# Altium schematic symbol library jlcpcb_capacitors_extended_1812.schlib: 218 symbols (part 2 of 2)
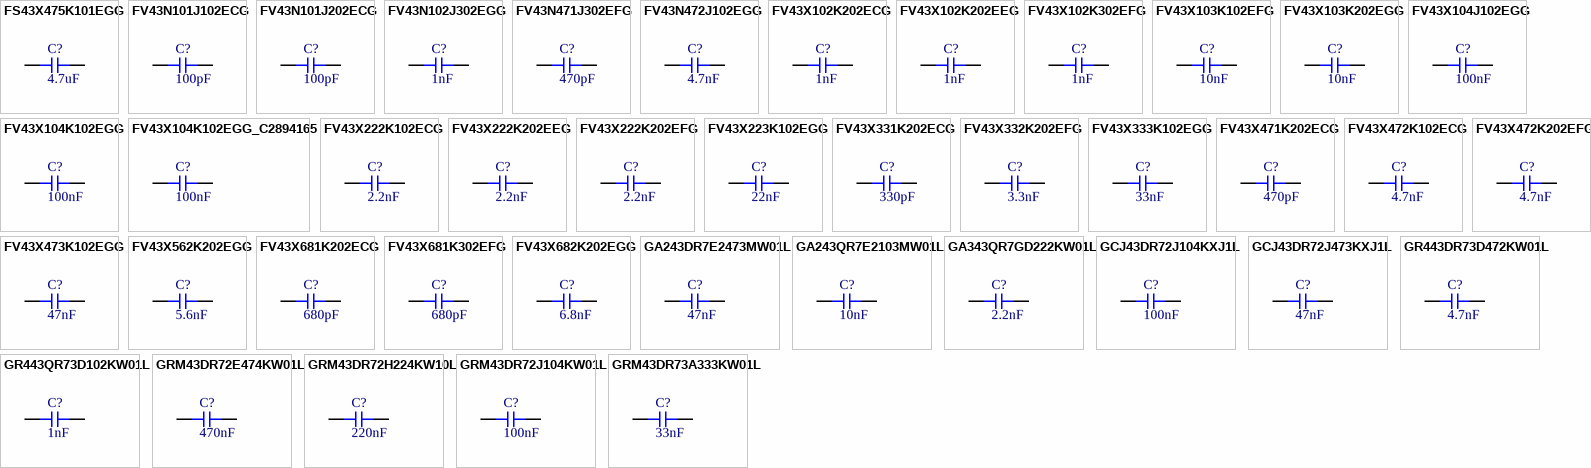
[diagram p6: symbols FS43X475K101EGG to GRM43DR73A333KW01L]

## FV43X333K102EGG
designator C?  Capacitance: 33nF  (hidden comment: *)
Capacitor, Ceramic (MLCC), 33nF, ±10%, 1kV, ±10%, SMD 1812; Manufacturer: PSA(Prosperity Dielectrics); Manufacturer Part Number: FV43X333K102EGG
footprint CAP-1812 (1812 (4532M) Capacitor)
pins: 1, 2

## FV43X471K202ECG
designator C?  Capacitance: 470pF  (hidden comment: *)
Capacitor, Ceramic (MLCC), 470pF, ±10%, 2kV, X7R, ±10%, SMD 1812; Manufacturer: PSA(Prosperity Dielectrics); Manufacturer Part Number: FV43X471K202ECG
footprint CAP-1812 (1812 (4532M) Capacitor)
pins: 1, 2

## FV43X472K102ECG
designator C?  Capacitance: 4.7nF  (hidden comment: *)
Capacitor, Ceramic (MLCC), 4.7nF, ±10%, 1kV, X7R, ±10%, SMD 1812; Manufacturer: PSA(Prosperity Dielectrics); Manufacturer Part Number: FV43X472K102ECG
footprint CAP-1812 (1812 (4532M) Capacitor)
pins: 1, 2

## FV43X472K202EFG
designator C?  Capacitance: 4.7nF  (hidden comment: *)
Capacitor, Ceramic (MLCC), 4.7nF, ±10%, 2kV, X7R, ±10%, SMD 1812; Manufacturer: PSA(Prosperity Dielectrics); Manufacturer Part Number: FV43X472K202EFG
footprint CAP-1812 (1812 (4532M) Capacitor)
pins: 1, 2

## FV43X473K102EGG
designator C?  Capacitance: 47nF  (hidden comment: *)
Capacitor, Ceramic (MLCC), 47nF, ±10%, 1kV, X7R, ±10%, SMD 1812; Manufacturer: PSA(Prosperity Dielectrics); Manufacturer Part Number: FV43X473K102EGG
footprint CAP-1812 (1812 (4532M) Capacitor)
pins: 1, 2

## FV43X562K202EGG
designator C?  Capacitance: 5.6nF  (hidden comment: *)
Capacitor, Ceramic (MLCC), 5.6nF, ±10%, 2kV, ±10%, SMD 1812; Manufacturer: PSA(Prosperity Dielectrics); Manufacturer Part Number: FV43X562K202EGG
footprint CAP-1812 (1812 (4532M) Capacitor)
pins: 1, 2

## FV43X681K202ECG
designator C?  Capacitance: 680pF  (hidden comment: *)
Capacitor, Ceramic (MLCC), 680pF, ±10%, 2kV, X7R, ±10%, SMD 1812; Manufacturer: PSA(Prosperity Dielectrics); Manufacturer Part Number: FV43X681K202ECG
footprint CAP-1812 (1812 (4532M) Capacitor)
pins: 1, 2

## FV43X681K302EFG
designator C?  Capacitance: 680pF  (hidden comment: *)
Capacitor, Ceramic (MLCC), 680pF, ±10%, 3kV, X7R, ±10%, SMD 1812; Manufacturer: PSA(Prosperity Dielectrics); Manufacturer Part Number: FV43X681K302EFG
footprint CAP-1812 (1812 (4532M) Capacitor)
pins: 1, 2

## FV43X682K202EGG
designator C?  Capacitance: 6.8nF  (hidden comment: *)
Capacitor, Ceramic (MLCC), 6.8nF, ±10%, 2kV, X7R, ±10%, SMD 1812; Manufacturer: PSA(Prosperity Dielectrics); Manufacturer Part Number: FV43X682K202EGG
footprint CAP-1812 (1812 (4532M) Capacitor)
pins: 1, 2

## GA243DR7E2473MW01L
designator C?  Capacitance: 47nF  (hidden comment: *)
Capacitor, Ceramic (MLCC), 47nF, ±20%, 250V, X7R, ±20%, SMD 1812; Manufacturer: Murata Electronics; Manufacturer Part Number: GA243DR7E2473MW01L
footprint CAP-1812 (1812 (4532M) Capacitor)
pins: 1, 2

## GA243QR7E2103MW01L
designator C?  Capacitance: 10nF  (hidden comment: *)
Capacitor, Ceramic (MLCC), 10nF, ±20%, 250V, X7R, ±20%, SMD 1812; Manufacturer: Murata Electronics; Manufacturer Part Number: GA243QR7E2103MW01L
footprint CAP-1812 (1812 (4532M) Capacitor)
pins: 1, 2

## GA343QR7GD222KW01L
designator C?  Capacitance: 2.2nF  (hidden comment: *)
Capacitor, Ceramic (MLCC), 2.2nF, ±10%, 250V, X7R, ±10%, SMD 1812; Manufacturer: Murata Electronics; Manufacturer Part Number: GA343QR7GD222KW01L
footprint CAP-1812 (1812 (4532M) Capacitor)
pins: 1, 2

## GCJ43DR72J104KXJ1L
designator C?  Capacitance: 100nF  (hidden comment: *)
Capacitor, Ceramic (MLCC), 100nF, ±10%, 630V, X7R, ±10%, SMD 1812; Manufacturer: Murata Electronics; Manufacturer Part Number: GCJ43DR72J104KXJ1L
footprint CAP-1812 (1812 (4532M) Capacitor)
pins: 1, 2

## GCJ43DR72J473KXJ1L
designator C?  Capacitance: 47nF  (hidden comment: *)
Capacitor, Ceramic (MLCC), 47nF, ±10%, 630V, X7R, ±10%, SMD 1812; Manufacturer: Murata Electronics; Manufacturer Part Number: GCJ43DR72J473KXJ1L
footprint CAP-1812 (1812 (4532M) Capacitor)
pins: 1, 2

## GR443DR73D472KW01L
designator C?  Capacitance: 4.7nF  (hidden comment: *)
Capacitor, Ceramic (MLCC), 4.7nF, ±10%, 2kV, X7R, ±10%, SMD 1812; Manufacturer: Murata Electronics; Manufacturer Part Number: GR443DR73D472KW01L
footprint CAP-1812 (1812 (4532M) Capacitor)
pins: 1, 2

## GR443QR73D102KW01L
designator C?  Capacitance: 1nF  (hidden comment: *)
Capacitor, Ceramic (MLCC), 1nF, ±10%, 2kV, X7R, ±10%, SMD 1812; Manufacturer: Murata Electronics; Manufacturer Part Number: GR443QR73D102KW01L
footprint CAP-1812 (1812 (4532M) Capacitor)
pins: 1, 2

## GRM43DR72E474KW01L
designator C?  Capacitance: 470nF  (hidden comment: *)
Capacitor, Ceramic (MLCC), 470nF, ±10%, 250V, X7R, ±10%, SMD 1812; Manufacturer: Murata Electronics; Manufacturer Part Number: GRM43DR72E474KW01L
footprint CAP-1812 (1812 (4532M) Capacitor)
pins: 1, 2

## GRM43DR72H224KW10L
designator C?  Capacitance: 220nF  (hidden comment: *)
Capacitor, Ceramic (MLCC), 220nF, ±10%, 500V, X7R, ±10%, SMD 1812; Manufacturer: Murata Electronics; Manufacturer Part Number: GRM43DR72H224KW10L
footprint CAP-1812 (1812 (4532M) Capacitor)
pins: 1, 2

## GRM43DR72J104KW01L
designator C?  Capacitance: 100nF  (hidden comment: *)
Capacitor, Ceramic (MLCC), 100nF, ±10%, 630V, X7R, ±10%, SMD 1812; Manufacturer: Murata Electronics; Manufacturer Part Number: GRM43DR72J104KW01L
footprint CAP-1812 (1812 (4532M) Capacitor)
pins: 1, 2

## GRM43DR73A333KW01L
designator C?  Capacitance: 33nF  (hidden comment: *)
Capacitor, Ceramic (MLCC), 33nF, ±10%, 1kV, X7R, ±10%, SMD 1812; Manufacturer: Murata Electronics; Manufacturer Part Number: GRM43DR73A333KW01L
footprint CAP-1812 (1812 (4532M) Capacitor)
pins: 1, 2

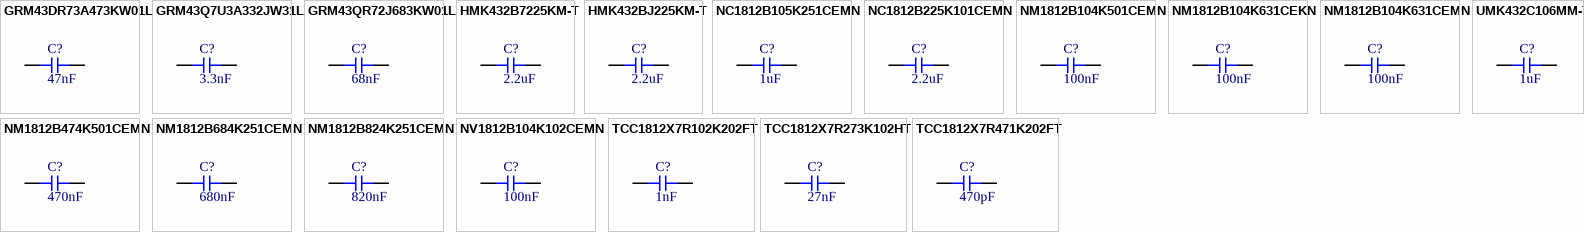
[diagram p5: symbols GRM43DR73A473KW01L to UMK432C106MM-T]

## GRM43DR73A473KW01L
designator C?  Capacitance: 47nF  (hidden comment: *)
Capacitor, Ceramic (MLCC), 47nF, ±10%, 1kV, X7R, ±10%, SMD 1812; Manufacturer: Murata Electronics; Manufacturer Part Number: GRM43DR73A473KW01L
footprint CAP-1812 (1812 (4532M) Capacitor)
pins: 1, 2

## GRM43Q7U3A332JW31L
designator C?  Capacitance: 3.3nF  (hidden comment: *)
Capacitor, Ceramic (MLCC), 3.3nF, ±5%, 1kV, U2J, ±5%, SMD 1812; Manufacturer: Murata Electronics; Manufacturer Part Number: GRM43Q7U3A332JW31L
footprint CAP-1812 (1812 (4532M) Capacitor)
pins: 1, 2

## GRM43QR72J683KW01L
designator C?  Capacitance: 68nF  (hidden comment: *)
Capacitor, Ceramic (MLCC), 68nF, ±10%, 630V, X7R, ±10%, SMD 1812; Manufacturer: Murata Electronics; Manufacturer Part Number: GRM43QR72J683KW01L
footprint CAP-1812 (1812 (4532M) Capacitor)
pins: 1, 2

## HMK432B7225KM-T
designator C?  Capacitance: 2.2uF  (hidden comment: *)
Capacitor, Ceramic (MLCC), 2.2uF, ±10%, 100V, X7R, ±10%, SMD 1812; Manufacturer: Taiyo Yuden; Manufacturer Part Number: HMK432B7225KM-T
footprint CAP-1812 (1812 (4532M) Capacitor)
pins: 1, 2

## HMK432BJ225KM-T
designator C?  Capacitance: 2.2uF  (hidden comment: *)
Capacitor, Ceramic (MLCC), 2.2uF, ±10%, 100V, X5R, ±10%, SMD 1812; Manufacturer: Taiyo Yuden; Manufacturer Part Number: HMK432BJ225KM-T
footprint CAP-1812 (1812 (4532M) Capacitor)
pins: 1, 2

## NC1812B105K251CEMN
designator C?  Capacitance: 1uF  (hidden comment: *)
Capacitor, Ceramic (MLCC), 1uF, ±10%, 250V, X7R, ±10%, SMD 1812; Manufacturer: HUI JU; Manufacturer Part Number: NC1812B105K251CEMN
footprint CAP-1812 (1812 (4532M) Capacitor)
pins: 1, 2

## NC1812B225K101CEMN
designator C?  Capacitance: 2.2uF  (hidden comment: *)
Capacitor, Ceramic (MLCC), 2.2uF, ±10%, 100V, X7R, ±10%, SMD 1812; Manufacturer: HUI JU; Manufacturer Part Number: NC1812B225K101CEMN
footprint CAP-1812 (1812 (4532M) Capacitor)
pins: 1, 2

## NM1812B104K501CEMN
designator C?  Capacitance: 100nF  (hidden comment: *)
Capacitor, Ceramic (MLCC), 100nF, ±10%, 500V, X7R, ±10%, SMD 1812; Manufacturer: HUI JU; Manufacturer Part Number: NM1812B104K501CEMN
footprint CAP-1812 (1812 (4532M) Capacitor)
pins: 1, 2

## NM1812B104K631CEKN
designator C?  Capacitance: 100nF  (hidden comment: *)
Capacitor, Ceramic (MLCC), 100nF, ±10%, 630V, X7R, ±10%, SMD 1812; Manufacturer: HUI JU; Manufacturer Part Number: NM1812B104K631CEKN
footprint CAP-1812 (1812 (4532M) Capacitor)
pins: 1, 2

## NM1812B104K631CEMN
designator C?  Capacitance: 100nF  (hidden comment: *)
Capacitor, Ceramic (MLCC), 100nF, ±10%, 630V, X7R, ±10%, SMD 1812; Manufacturer: HUI JU; Manufacturer Part Number: NM1812B104K631CEMN
footprint CAP-1812 (1812 (4532M) Capacitor)
pins: 1, 2

## NM1812B474K501CEMN
designator C?  Capacitance: 470nF  (hidden comment: *)
Capacitor, Ceramic (MLCC), 470nF, ±10%, 500V, ±10%, SMD 1812; Manufacturer: HUI JU; Manufacturer Part Number: NM1812B474K501CEMN
footprint CAP-1812 (1812 (4532M) Capacitor)
pins: 1, 2

## NM1812B684K251CEMN
designator C?  Capacitance: 680nF  (hidden comment: *)
Capacitor, Ceramic (MLCC), 680nF, ±10%, 250V, X7R, ±10%, SMD 1812; Manufacturer: HUI JU; Manufacturer Part Number: NM1812B684K251CEMN
footprint CAP-1812 (1812 (4532M) Capacitor)
pins: 1, 2

## NM1812B824K251CEMN
designator C?  Capacitance: 820nF  (hidden comment: *)
Capacitor, Ceramic (MLCC), 820nF, ±10%, 250V, X7R, ±10%, SMD 1812; Manufacturer: HUI JU; Manufacturer Part Number: NM1812B824K251CEMN
footprint CAP-1812 (1812 (4532M) Capacitor)
pins: 1, 2

## NV1812B104K102CEMN
designator C?  Capacitance: 100nF  (hidden comment: *)
Capacitor, Ceramic (MLCC), 100nF, ±10%, 1kV, X7R, ±10%, SMD 1812; Manufacturer: HUI JU; Manufacturer Part Number: NV1812B104K102CEMN
footprint CAP-1812 (1812 (4532M) Capacitor)
pins: 1, 2

## TCC1812X7R102K202FT
designator C?  Capacitance: 1nF  (hidden comment: *)
Capacitor, Ceramic (MLCC), 1nF, ±10%, 2kV, X7R, ±10%, SMD 1812; Manufacturer: CCTC; Manufacturer Part Number: TCC1812X7R102K202FT
footprint CAP-1812 (1812 (4532M) Capacitor)
pins: 1, 2

## TCC1812X7R273K102HT
designator C?  Capacitance: 27nF  (hidden comment: *)
Capacitor, Ceramic (MLCC), 27nF, ±10%, 1kV, X7R, ±10%, SMD 1812; Manufacturer: CCTC; Manufacturer Part Number: TCC1812X7R273K102HT
footprint CAP-1812 (1812 (4532M) Capacitor)
pins: 1, 2

## TCC1812X7R471K202FT
designator C?  Capacitance: 470pF  (hidden comment: *)
Capacitor, Ceramic (MLCC), 470pF, ±10%, 2kV, X7R, ±10%, SMD 1812; Manufacturer: CCTC; Manufacturer Part Number: TCC1812X7R471K202FT
footprint CAP-1812 (1812 (4532M) Capacitor)
pins: 1, 2

## UMK432C106MM-T
designator C?  Capacitance: 1uF  (hidden comment: *)
Capacitor, Ceramic (MLCC), 1uF, ±22%, X6S, ±22%, SMD 1812; Manufacturer: Taiyo Yuden; Manufacturer Part Number: UMK432C106MM-T
footprint CAP-1812 (1812 (4532M) Capacitor)
pins: 1, 2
